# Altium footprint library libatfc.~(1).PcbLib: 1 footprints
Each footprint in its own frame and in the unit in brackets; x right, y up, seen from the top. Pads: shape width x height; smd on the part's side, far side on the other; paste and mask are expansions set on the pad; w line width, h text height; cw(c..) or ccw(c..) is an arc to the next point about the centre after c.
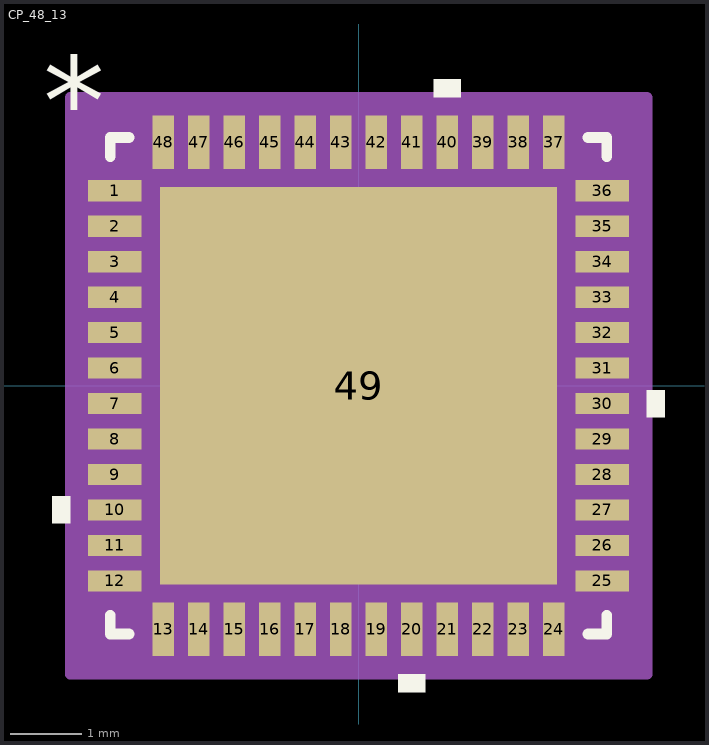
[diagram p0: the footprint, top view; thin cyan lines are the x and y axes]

## CP_48_13 [mm]
pads (49):
  rect 0.755x0.3 smd: 1(-3.433,2.75) 2(-3.433,2.25) 3(-3.433,1.75) 4(-3.433,1.25) 5(-3.433,0.75) 6(-3.433,0.25) 7(-3.433,-0.25) 8(-3.433,-0.75) 9(-3.433,-1.25) 10(-3.433,-1.75) 11(-3.433,-2.25) 12(-3.433,-2.75) 25(3.433,-2.75) 26(3.433,-2.25) 27(3.433,-1.75) 28(3.433,-1.25) 29(3.433,-0.75) 30(3.433,-0.25) 31(3.433,0.25) 32(3.433,0.75) 33(3.433,1.25) 34(3.433,1.75) 35(3.433,2.25) 36(3.433,2.75)
  rect 0.3x0.755 smd: 13(-2.75,-3.433) 14(-2.25,-3.433) 15(-1.75,-3.433) 16(-1.25,-3.433) 17(-0.75,-3.433) 18(-0.25,-3.433) 19(0.25,-3.433) 20(0.75,-3.433) 21(1.25,-3.433) 22(1.75,-3.433) 23(2.25,-3.433) 24(2.75,-3.433) 37(2.75,3.433) 38(2.25,3.433) 39(1.75,3.433) 40(1.25,3.433) 41(0.75,3.433) 42(0.25,3.433) 43(-0.25,3.433) 44(-0.75,3.433) 45(-1.25,3.433) 46(-1.75,3.433) 47(-2.25,3.433) 48(-2.75,3.433)
  rect 5.6x5.6 smd mask-2.781: 49(0,0)
Top Overlay:
  region: 1.441,4.064 1.06,4.064 1.06,4.318 1.441,4.318
  region: 4.064,-0.059 4.318,-0.059 4.318,-0.44 4.064,-0.44
  region: 0.941,-4.064 0.56,-4.064 0.56,-4.318 0.941,-4.318
  region: -4.064,-1.559 -4.318,-1.559 -4.318,-1.94 -4.064,-1.94
  lines w0.152: -3.5,-3.233 -3.5,-3.5 -3.233,-3.5 ; -3.5,3.233 -3.5,3.5 -3.233,3.5 ; 3.233,-3.5 3.5,-3.5 3.5,-3.233 ; 3.233,3.5 3.5,3.5 3.5,3.233
  text "*" at -4.445,3.381 h1.27
Mechanical 13:
  text "*" at -4.445,3.381 h1.27
Mechanical 15:
  region: 4.064,-4.064 -4.064,-4.064 -4.064,4.064 4.064,4.064
  lines w0.152: -4.064,-4.064 4.064,-4.064 4.064,4.064 -4.064,4.064 -4.064,-4.064
3D body: height 0.25, standoff 0, extent 0,0 0.254,0.254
